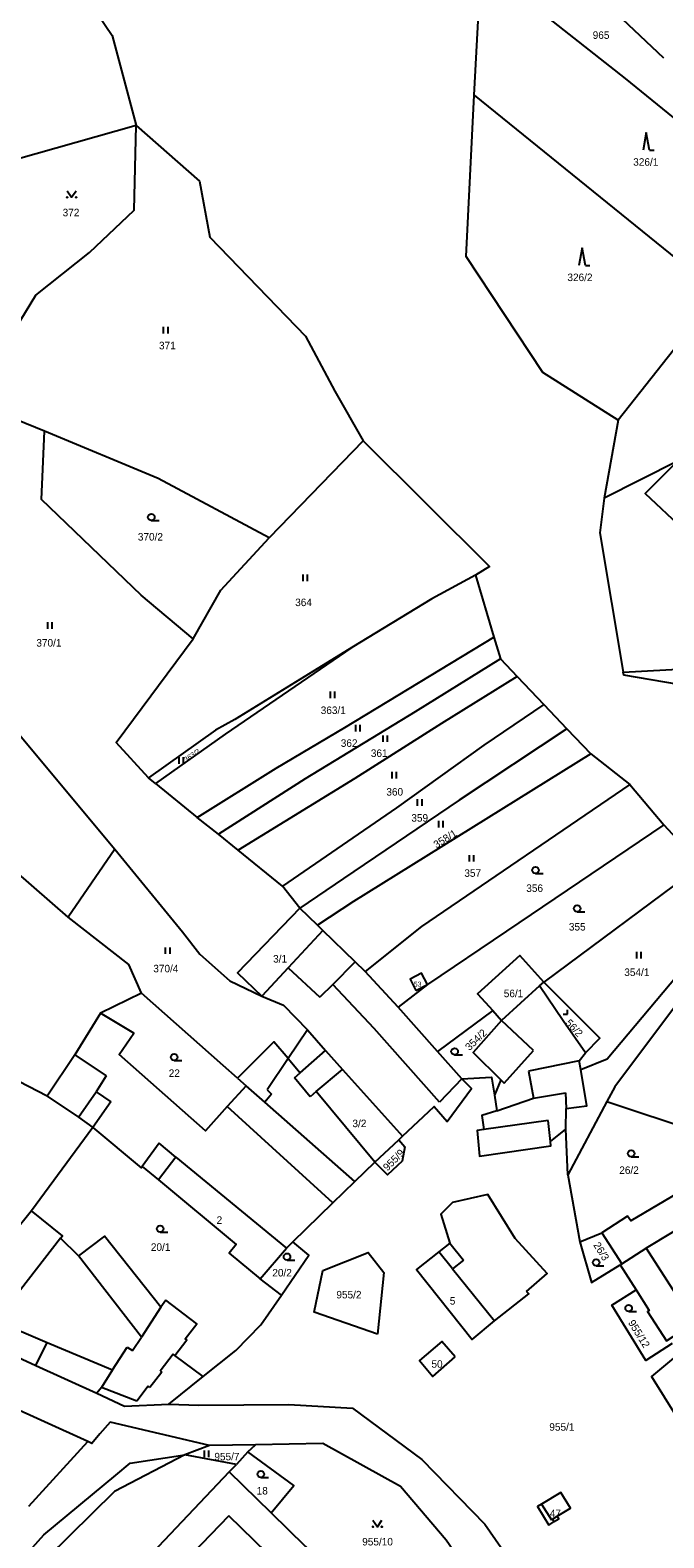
# Model space of a CAD drawing. Extents: x -7476540 to -746055, y -11317203 to -1129777.
# Drawn here: x -747956.4 to -747812.8, y -1130986.6 to -1130645.3 of the extents above; entities that cross this region are included whole.
import ezdxf

# ---------------------------------------------------------------- set-up
doc = ezdxf.new("R2010")
doc.units = 0
for name, color, linetype in [('Hranice parcel', 7, 'Continuous'), ('Parcelní čísla', 7, 'Continuous'), ('Vnitřní kresba', 7, 'Continuous'), ('Značky kultur', 7, 'Continuous')]:
    doc.layers.add(name, color=color, linetype=linetype)

msp = doc.modelspace()

# ---------------------------------------------------------------- linework, layer by layer
at = {"layer": 'Hranice parcel'}
for p, q in [((-747855.76, -1130660), (-747854.2, -1130630.54)), ((-747855.76, -1130660), (-747798.81, -1130706.12)), ((-747932.35, -1130666.92), (-747959.56, -1130674.56)), ((-747953.15, -1130736.09), (-747968.32, -1130729.96)), ((-747823.18, -1130733.56), (-747826.34, -1130751.29)), ((-747880.96, -1130738.26), (-747902.23, -1130760.25)), ((-747809.75, -1130742.85), (-747826.34, -1130751.29)), ((-747855.52, -1130768.71), (-747851.3, -1130782.72)), ((-747985.28, -1130773.23), (-747937.23, -1130830.7)), ((-747851.3, -1130782.72), (-747849.81, -1130787.66)), ((-747849.81, -1130787.66), (-747846.02, -1130791.65)), ((-747846.02, -1130791.65), (-747840.01, -1130797.96)), ((-747840.01, -1130797.96), (-747834.77, -1130803.46)), ((-747834.77, -1130803.46), (-747829.36, -1130809.14)), ((-747829.36, -1130809.14), (-747820.55, -1130816.09)), ((-747927.97, -1130815.84), (-747929.55, -1130814.55)), ((-747927.97, -1130815.84), (-747918.56, -1130823.54)), ((-747820.55, -1130816.09), (-747812.81, -1130825.22)), ((-747913.69, -1130827.28), (-747918.56, -1130823.54)), ((-747812.81, -1130825.22), (-747804.38, -1130834.32)), ((-747909.27, -1130830.92), (-747913.69, -1130827.28)), ((-747937.23, -1130830.7), (-747947.78, -1130846.14)), ((-747899.19, -1130839.1), (-747909.27, -1130830.92)), ((-747804.38, -1130834.32), (-747840.03, -1130860.79)), ((-747895.31, -1130844.05), (-747899.19, -1130839.1)), ((-747891.29, -1130847.94), (-747895.31, -1130844.05)), ((-747873.03, -1130866.5), (-747880.46, -1130858.39)), ((-747931.2, -1130863.28), (-747940.47, -1130867.84)), ((-747864.12, -1130876.49), (-747873.03, -1130866.5)), ((-747851.6, -1130867.26), (-747864.12, -1130876.49)), ((-747851.6, -1130867.26), (-747849.58, -1130869.48)), ((-747858.58, -1130882.72), (-747864.12, -1130876.49)), ((-747909.4, -1130882.58), (-747907.48, -1130884.27)), ((-747825.73, -1130887.83), (-747834.6, -1130904.4)), ((-747825.73, -1130887.83), (-747793.01, -1130898.76)), ((-747942.19, -1130893.69), (-747956.08, -1130912.6)), ((-747834.6, -1130904.4), (-747834.99, -1130894.09)), ((-747878.28, -1130901.53), (-747872.89, -1130896.5)), ((-747872.89, -1130896.5), (-747872.04, -1130895.7)), ((-747882.81, -1130905.92), (-747878.28, -1130901.53)), ((-747834.6, -1130904.4), (-747831.83, -1130919.6)), ((-747956.08, -1130912.6), (-747974.9, -1130935.77)), ((-747831.83, -1130919.6), (-747826.88, -1130917.6)), ((-747826.88, -1130917.6), (-747822.35, -1130924.58)), ((-747822.35, -1130924.58), (-747822.73, -1130924.82)), ((-747822.73, -1130924.82), (-747819.12, -1130930.45)), ((-747899.44, -1130931.65), (-747904.3, -1130927.98)), ((-747917.18, -1130950.1), (-747923.65, -1130945.33)), ((-747924.97, -1130956.33), (-747917.18, -1130950.1)), ((-747956.74, -1130979.41), (-747943.32, -1130964.83)), ((-747915.76, -1130965.72), (-747921.38, -1130967.81)), ((-747905.36, -1130965.53), (-747915.76, -1130965.72)), ((-747907.05, -1130967.14), (-747905.36, -1130965.53)), ((-747909.68, -1130969.99), (-747921.38, -1130967.81)), ((-747907.05, -1130967.14), (-747909.68, -1130969.99)), ((-747911.3, -1130971.64), (-747909.68, -1130969.99)), ((-747901.77, -1130980.96), (-747911.3, -1130971.64))]:
    msp.add_line(p, q, dxfattribs=at)
for points in [[(-747812.8, -1130651.64), (-747826.2, -1130639.05), (-747848.84, -1130625.02)], [(-747948.65, -1130630.54), (-747937.8, -1130646.48), (-747932.35, -1130666.92)], [(-747854.2, -1130630.54), (-747821.59, -1130656.28), (-747772.81, -1130695.9)], [(-747823.18, -1130733.56), (-747840.23, -1130722.79), (-747857.62, -1130696.55), (-747855.76, -1130660)], [(-747965.59, -1130718.16), (-747963.47, -1130718.96), (-747955.1, -1130705.31), (-747942.97, -1130695.63), (-747932.86, -1130686.09), (-747932.35, -1130666.92)], [(-747932.35, -1130666.92), (-747918.04, -1130679.51), (-747915.7, -1130692.18), (-747894.02, -1130714.58), (-747887.33, -1130727.05), (-747880.96, -1130738.26)], [(-747805.74, -1130716.29), (-747810.6, -1130717.76), (-747823.18, -1130733.56)], [(-747919.46, -1130783.07), (-747931.23, -1130773.21), (-747953.83, -1130751.57), (-747953.15, -1130736.09)], [(-747902.23, -1130760.25), (-747927.4, -1130746.77), (-747953.15, -1130736.09)], [(-747880.96, -1130738.26), (-747852.28, -1130766.74), (-747855.52, -1130768.71)], [(-747809.75, -1130742.85), (-747817.01, -1130750.2), (-747808.52, -1130758.22), (-747792.09, -1130768.69), (-747784.71, -1130772.17)], [(-747826.34, -1130751.29), (-747827.34, -1130759.1), (-747822, -1130790.67)], [(-747919.46, -1130783.07), (-747913.2, -1130772.11), (-747902.23, -1130760.25)], [(-747855.52, -1130768.71), (-747865.41, -1130774.06), (-747883.52, -1130785.07)], [(-747822, -1130790.67), (-747782.01, -1130788.46), (-747784.71, -1130772.17)], [(-747929.55, -1130814.55), (-747936.92, -1130806.6), (-747919.46, -1130783.07)], [(-747918.56, -1130823.54), (-747900.68, -1130812.35), (-747885.1, -1130803.15), (-747851.3, -1130782.72)], [(-747883.52, -1130785.07), (-747910.03, -1130801.35), (-747914.38, -1130803.79), (-747929.55, -1130814.55)], [(-747883.52, -1130785.07), (-747912.25, -1130804.68), (-747927.97, -1130815.84)], [(-747849.81, -1130787.66), (-747869.15, -1130799.59), (-747894.06, -1130814.79), (-747913.69, -1130827.28)], [(-747846.02, -1130791.65), (-747863.17, -1130802.29), (-747882.81, -1130814.71), (-747909.27, -1130830.92)], [(-747754.53, -1130790.17), (-747777.03, -1130805.89), (-747790.88, -1130796.57), (-747821.89, -1130791.29), (-747822, -1130790.67)], [(-747840.01, -1130797.96), (-747853.58, -1130807.15), (-747873.39, -1130821.38), (-747899.19, -1130839.1)], [(-747834.77, -1130803.46), (-747859.22, -1130819.6), (-747885.37, -1130837.32), (-747895.31, -1130844.05)], [(-747947.78, -1130846.14), (-747959.65, -1130835.75), (-748001.98, -1130807.92)], [(-747829.36, -1130809.14), (-747883.17, -1130842.59), (-747891.29, -1130847.94)], [(-747820.55, -1130816.09), (-747867.74, -1130848.23), (-747880.46, -1130858.39)], [(-747812.81, -1130825.22), (-747848.46, -1130849.27), (-747866.39, -1130861.37), (-747873.03, -1130866.5)], [(-747937.23, -1130830.7), (-747921.89, -1130849.4), (-747917.99, -1130854.46), (-747911.17, -1130860.49), (-747903.93, -1130864)], [(-747952.53, -1130886.62), (-747963.27, -1130881.1), (-747989.61, -1130862.33), (-748011.06, -1130841.51), (-748016.47, -1130840.3)], [(-747931.2, -1130863.28), (-747934.04, -1130856.8), (-747947.78, -1130846.14)], [(-747895.31, -1130844.05), (-747909.44, -1130858.68), (-747903.93, -1130864)], [(-747831.64, -1130880.59), (-747825.65, -1130878.15), (-747808.21, -1130857.46), (-747795.63, -1130843.76)], [(-747880.46, -1130858.39), (-747882.73, -1130856.2), (-747890.05, -1130849.13), (-747891.29, -1130847.94)], [(-747751.43, -1130846.33), (-747786.35, -1130849.61), (-747800.53, -1130857.22), (-747810.62, -1130866.79), (-747823.91, -1130884.54), (-747825.73, -1130887.83)], [(-747840.03, -1130860.79), (-747845.48, -1130854.8), (-747855.03, -1130863.49), (-747851.6, -1130867.26)], [(-747868.98, -1130862.72), (-747866.39, -1130861.37), (-747867.74, -1130858.78), (-747870.26, -1130860.14), (-747868.98, -1130862.72)], [(-747909.4, -1130882.58), (-747912.7, -1130879.65), (-747931.2, -1130863.28)], [(-747830.59, -1130876.82), (-747835.61, -1130869.57), (-747840.96, -1130861.66), (-747840.03, -1130860.79)], [(-747830.59, -1130876.82), (-747827.3, -1130873.5), (-747840.03, -1130860.79)], [(-747903.93, -1130864), (-747898.96, -1130866.03), (-747893.59, -1130871.58)], [(-747940.47, -1130867.84), (-747946.29, -1130877.28), (-747952.53, -1130886.62)], [(-747907.48, -1130884.27), (-747911.73, -1130888.98), (-747916.7, -1130894.49), (-747936.25, -1130877.17), (-747932.92, -1130872.33), (-747940.47, -1130867.84)], [(-747849.58, -1130869.48), (-747856.02, -1130876.74), (-747849.73, -1130882.95), (-747851.22, -1130886.4)], [(-747893.59, -1130871.58), (-747897.97, -1130878.1), (-747901.18, -1130874.36), (-747909.4, -1130882.58)], [(-747893.59, -1130871.58), (-747889.47, -1130876.3), (-747885.64, -1130880.57), (-747872.04, -1130895.7)], [(-747831.64, -1130880.59), (-747832, -1130878.65), (-747830.59, -1130876.82)], [(-747872.04, -1130895.7), (-747864.89, -1130888.95), (-747861.93, -1130892.38), (-747856.4, -1130884.91), (-747858.58, -1130882.72)], [(-747858.58, -1130882.72), (-747851.86, -1130882.31), (-747851.22, -1130886.4)], [(-747834.99, -1130894.09), (-747834.94, -1130889.44), (-747830.29, -1130888.84), (-747831.64, -1130880.59)], [(-747952.53, -1130886.62), (-747945.42, -1130891.38), (-747942.19, -1130893.69)], [(-747882.81, -1130905.92), (-747903.24, -1130887.99), (-747907.48, -1130884.27)], [(-747851.22, -1130886.4), (-747850.63, -1130889.96), (-747854.03, -1130890.99), (-747853.59, -1130894.17), (-747855.12, -1130894.39), (-747854.58, -1130900.2), (-747838.4, -1130897.9), (-747838.48, -1130896.91), (-747834.99, -1130894.09)], [(-747942.19, -1130893.69), (-747931.25, -1130902.83), (-747930.99, -1130902.52), (-747927.35, -1130905.55), (-747909.73, -1130920.21), (-747911.33, -1130922.13), (-747904.3, -1130927.98)], [(-747872.89, -1130896.5), (-747871.47, -1130898.11), (-747872.07, -1130901.37), (-747875.4, -1130904.41), (-747878.28, -1130901.53)], [(-747793.01, -1130898.76), (-747820.31, -1130914.83), (-747821.04, -1130913.77), (-747826.88, -1130917.6)], [(-747896.9, -1130919.58), (-747887.85, -1130910.81), (-747882.81, -1130905.92)], [(-747843.9, -1130930.84), (-747839.22, -1130926.8), (-747846.52, -1130918.84), (-747852.72, -1130908.9), (-747860.71, -1130910.68), (-747863.35, -1130913.36), (-747861.32, -1130919.89), (-747863.78, -1130921.85), (-747868.87, -1130925.9), (-747856.24, -1130941.74), (-747851.16, -1130937.49), (-747843.41, -1130931.39), (-747843.9, -1130930.84)], [(-747925.67, -1130932.84), (-747926.76, -1130934.36), (-747939.55, -1130918.32), (-747945.43, -1130922.74), (-747949.51, -1130918.78), (-747949.09, -1130918.27), (-747956.08, -1130912.6)], [(-747943.32, -1130964.83), (-747980.23, -1130948.11), (-748009.46, -1130932.87), (-748022.64, -1130922.41), (-748027.06, -1130916.24)], [(-747904.3, -1130927.98), (-747898.32, -1130921.01), (-747896.9, -1130919.58)], [(-747899.44, -1130931.65), (-747893.27, -1130922.65), (-747896.9, -1130919.58)], [(-747831.83, -1130919.6), (-747829.18, -1130928.84), (-747822.73, -1130924.82)], [(-747822.35, -1130924.58), (-747816.84, -1130921.05), (-747810.2, -1130931.39)], [(-747877.73, -1130940.47), (-747892.05, -1130935.51), (-747890.11, -1130926.12), (-747879.78, -1130921.99), (-747876.24, -1130926.56), (-747877.73, -1130940.47)], [(-747917.18, -1130950.1), (-747909.76, -1130944.17), (-747904.14, -1130938.37), (-747899.44, -1130931.65)], [(-747810.92, -1130942.58), (-747816.91, -1130946.43), (-747824.59, -1130933.96), (-747819.12, -1130930.45)], [(-747819.12, -1130930.45), (-747816.13, -1130935.12), (-747816.51, -1130935.36), (-747812.22, -1130942.04), (-747798.61, -1130933.2)], [(-747923.65, -1130945.33), (-747920.91, -1130941.82), (-747921.26, -1130941.54), (-747918.64, -1130938.18), (-747925.67, -1130932.84)], [(-747974.9, -1130935.77), (-747975.53, -1130936.55), (-747967.6, -1130941.88), (-747955.12, -1130947.63), (-747941.28, -1130953.85), (-747935.01, -1130956.79), (-747924.97, -1130956.33)], [(-747860.11, -1130945.6), (-747863.09, -1130942.14), (-747868.17, -1130946.48), (-747865.14, -1130950.05), (-747860.11, -1130945.6)], [(-747809.25, -1130944.84), (-747815.62, -1130950.1), (-747806.65, -1130964.52), (-747799.54, -1130960.27)], [(-747924.97, -1130956.33), (-747918.19, -1130956.61), (-747897.81, -1130956.39), (-747883.35, -1130957.23), (-747867.68, -1130968.89), (-747853.38, -1130983.52), (-747843.2, -1130998.16), (-747832.03, -1131034.24), (-747827.69, -1131050.62), (-747823.07, -1131065.32)], [(-747915.76, -1130965.72), (-747938.3, -1130960.4), (-747940.61, -1130963.08), (-747942.46, -1130965.22), (-747943.32, -1130964.83)], [(-747832.63, -1131062.43), (-747842.17, -1131030.42), (-747852.24, -1131001.44), (-747862.12, -1130987.14), (-747872.45, -1130974.99), (-747890.11, -1130965.25), (-747905.36, -1130965.53)], [(-747980.93, -1131019.45), (-747968.09, -1131002.39), (-747962.23, -1130995.86), (-747953.3, -1130985.9), (-747936.97, -1130972.39), (-747933.73, -1130969.71), (-747921.38, -1130967.81)], [(-747921.38, -1130967.81), (-747937.31, -1130976.12), (-747967.89, -1131006.15), (-747980.93, -1131019.45)], [(-747901.77, -1130980.96), (-747896.66, -1130974.79), (-747907.05, -1130967.14)], [(-747911.3, -1130971.64), (-747939.39, -1131001.36), (-747946.28, -1131008.68)], [(-747838.9, -1130983.72), (-747837.64, -1130982.94), (-747836.63, -1130982.32), (-747836.99, -1130981.73), (-747833.96, -1130979.87), (-747836.13, -1130976.33), (-747840.51, -1130978.98), (-747841.46, -1130979.55), (-747838.9, -1130983.72)], [(-747893.47, -1130989.15), (-747893.98, -1130988.57), (-747901.77, -1130980.96)]]:
    msp.add_lwpolyline(points, dxfattribs=at)
at = {"layer": 'Vnitřní kresba'}
for p, q in [((-747890.05, -1130849.13), (-747897.92, -1130857.56)), ((-747887.82, -1130861.32), (-747882.73, -1130856.2)), ((-747897.92, -1130857.56), (-747903.93, -1130864)), ((-747897.92, -1130857.56), (-747890.77, -1130864.23)), ((-747887.82, -1130861.32), (-747890.77, -1130864.23)), ((-747878.46, -1130871.28), (-747887.82, -1130861.32)), ((-747840.96, -1130861.66), (-747849.58, -1130869.48)), ((-747842.34, -1130876.27), (-747849.58, -1130869.48)), ((-747863.67, -1130887.95), (-747878.46, -1130871.28)), ((-747895.21, -1130881.31), (-747889.47, -1130876.3)), ((-747848.96, -1130883.68), (-747842.34, -1130876.27)), ((-747946.29, -1130877.28), (-747939.2, -1130881.99)), ((-747897.97, -1130878.1), (-747902.71, -1130885.17)), ((-747897.97, -1130878.1), (-747895.21, -1130881.31)), ((-747832, -1130878.65), (-747843.45, -1130880.95)), ((-747939.2, -1130881.99), (-747941.45, -1130885.62)), ((-747896.52, -1130882.45), (-747895.21, -1130881.31)), ((-747892.98, -1130886.77), (-747896.52, -1130882.45)), ((-747891.57, -1130885.56), (-747885.64, -1130880.57)), ((-747858.58, -1130882.72), (-747863.67, -1130887.95)), ((-747849.73, -1130882.95), (-747848.96, -1130883.68)), ((-747843.45, -1130880.95), (-747842.38, -1130887.09)), ((-747945.42, -1130891.38), (-747941.45, -1130885.62)), ((-747941.45, -1130885.62), (-747938.14, -1130887.93)), ((-747901.69, -1130886.19), (-747903.24, -1130887.99)), ((-747902.71, -1130885.17), (-747901.69, -1130886.19)), ((-747891.57, -1130885.56), (-747892.98, -1130886.77)), ((-747878.28, -1130901.53), (-747891.57, -1130885.56)), ((-747850.63, -1130889.96), (-747842.38, -1130887.09)), ((-747842.38, -1130887.09), (-747835.08, -1130885.88)), ((-747835.08, -1130885.88), (-747834.94, -1130889.44)), ((-747938.14, -1130887.93), (-747942.19, -1130893.69)), ((-747887.85, -1130910.81), (-747911.73, -1130888.98)), ((-747839.02, -1130892.13), (-747853.59, -1130894.17)), ((-747838.48, -1130896.91), (-747839.02, -1130892.13)), ((-747927.18, -1130897.3), (-747930.99, -1130902.52)), ((-747923.37, -1130900.43), (-747927.18, -1130897.3)), ((-747923.37, -1130900.43), (-747927.35, -1130905.55)), ((-747923.37, -1130900.43), (-747898.32, -1130921.01)), ((-747786.33, -1130902.63), (-747816.84, -1130921.05)), ((-747949.51, -1130918.78), (-747964.11, -1130937.48)), ((-747861.32, -1130919.89), (-747858.22, -1130923.72)), ((-747931.2, -1130941.16), (-747945.43, -1130922.74)), ((-747860.68, -1130925.7), (-747863.78, -1130921.85)), ((-747858.22, -1130923.72), (-747860.68, -1130925.7)), ((-747860.68, -1130925.7), (-747851.16, -1130937.49)), ((-747926.76, -1130934.36), (-747931.2, -1130941.16)), ((-747964.11, -1130937.48), (-747952.52, -1130942.42)), ((-747933.19, -1130944.19), (-747931.2, -1130941.16)), ((-747955.12, -1130947.63), (-747952.52, -1130942.42)), ((-747952.52, -1130942.42), (-747937.72, -1130948.61)), ((-747937.72, -1130948.61), (-747934.42, -1130943.46)), ((-747934.42, -1130943.46), (-747933.19, -1130944.19)), ((-747924, -1130945.06), (-747926.95, -1130948.85)), ((-747923.65, -1130945.33), (-747924, -1130945.06)), ((-747937.72, -1130948.61), (-747940.26, -1130952.54)), ((-747926.6, -1130949.12), (-747929.28, -1130952.56)), ((-747926.95, -1130948.85), (-747926.6, -1130949.12)), ((-747940.26, -1130952.54), (-747941.28, -1130953.85)), ((-747932.25, -1130955.65), (-747940.26, -1130952.54)), ((-747929.63, -1130952.29), (-747932.25, -1130955.65)), ((-747929.28, -1130952.56), (-747929.63, -1130952.29)), ((-747840.51, -1130978.98), (-747838.26, -1130982.51)), ((-747911.42, -1130981.63), (-747934.8, -1131005.8)), ((-747902.74, -1130990.02), (-747911.42, -1130981.63)), ((-747838.26, -1130982.51), (-747838.01, -1130982.35)), ((-747838.01, -1130982.35), (-747836.99, -1130981.73)), ((-747838.01, -1130982.35), (-747837.64, -1130982.94))]:
    msp.add_line(p, q, dxfattribs=at)
at = {"layer": 'Značky kultur'}
for p, q in [((-747816.78, -1130668.45), (-747817.53, -1130672.45)), ((-747816.03, -1130672.45), (-747816.78, -1130668.45)), ((-747816.03, -1130672.45), (-747815.03, -1130672.45)), ((-747831.32, -1130694.56), (-747832.07, -1130698.56)), ((-747830.57, -1130698.56), (-747831.32, -1130694.56)), ((-747830.57, -1130698.56), (-747829.57, -1130698.56)), ((-747926.16, -1130714), (-747926.16, -1130712.5)), ((-747925.16, -1130714), (-747925.16, -1130712.5)), ((-747928.95, -1130756.3), (-747927.2, -1130756.3)), ((-747894.53, -1130770.07), (-747894.53, -1130768.57)), ((-747893.53, -1130770.07), (-747893.53, -1130768.57)), ((-747952.41, -1130780.84), (-747952.41, -1130779.34)), ((-747951.41, -1130780.84), (-747951.41, -1130779.34)), ((-747888.33, -1130796.55), (-747888.33, -1130795.05)), ((-747887.33, -1130796.55), (-747887.33, -1130795.05)), ((-747882.59, -1130804.06), (-747882.59, -1130802.56)), ((-747881.59, -1130804.06), (-747881.59, -1130802.56)), ((-747876.43, -1130806.45), (-747876.43, -1130804.95)), ((-747875.43, -1130806.45), (-747875.43, -1130804.95)), ((-747922.64, -1130811.41), (-747922.64, -1130809.91)), ((-747921.64, -1130811.41), (-747921.64, -1130809.91)), ((-747874.4, -1130814.73), (-747874.4, -1130813.23)), ((-747873.4, -1130814.73), (-747873.4, -1130813.23)), ((-747868.61, -1130820.93), (-747868.61, -1130819.43)), ((-747867.61, -1130820.93), (-747867.61, -1130819.43)), ((-747863.81, -1130825.77), (-747863.81, -1130824.27)), ((-747862.81, -1130825.77), (-747862.81, -1130824.27)), ((-747856.86, -1130833.54), (-747856.86, -1130832.04)), ((-747855.86, -1130833.54), (-747855.86, -1130832.04)), ((-747841.92, -1130836.24), (-747840.17, -1130836.24)), ((-747832.44, -1130844.88), (-747830.69, -1130844.88)), ((-747925.71, -1130854.44), (-747925.71, -1130852.94)), ((-747924.71, -1130854.44), (-747924.71, -1130852.94)), ((-747818.95, -1130855.49), (-747818.95, -1130853.99)), ((-747817.95, -1130855.49), (-747817.95, -1130853.99)), ((-747835.66, -1130868.06), (-747834.66, -1130868.06)), ((-747834.66, -1130868.06), (-747834.66, -1130867.06)), ((-747923.77, -1130878.57), (-747922.02, -1130878.57)), ((-747860.22, -1130877.25), (-747858.47, -1130877.25)), ((-747820.23, -1130900.36), (-747818.48, -1130900.36)), ((-747926.92, -1130917.42), (-747925.17, -1130917.42)), ((-747898.2, -1130923.72), (-747896.45, -1130923.72)), ((-747828.13, -1130925.05), (-747826.38, -1130925.05)), ((-747820.78, -1130935.39), (-747819.03, -1130935.39)), ((-747916.89, -1130968.34), (-747916.89, -1130966.84)), ((-747915.89, -1130968.34), (-747915.89, -1130966.84)), ((-747904.13, -1130972.92), (-747902.38, -1130972.92))]:
    msp.add_line(p, q, dxfattribs=at)
for points in [[(-747948.01, -1130681.65), (-747947.01, -1130683.15), (-747946.01, -1130681.65)], [(-747878.72, -1130982.59), (-747877.72, -1130984.09), (-747876.72, -1130982.59)]]:
    msp.add_lwpolyline(points, dxfattribs=at)
for centre, radius in [((-747948.01, -1130683.15), 0.1), ((-747946.01, -1130683.15), 0.1), ((-747928.95, -1130755.55), 0.75), ((-747841.92, -1130835.49), 0.75), ((-747832.44, -1130844.13), 0.75), ((-747860.22, -1130876.5), 0.75), ((-747923.77, -1130877.82), 0.75), ((-747820.23, -1130899.61), 0.75), ((-747926.92, -1130916.67), 0.75), ((-747898.2, -1130922.97), 0.75), ((-747828.13, -1130924.3), 0.75), ((-747820.78, -1130934.64), 0.75), ((-747904.13, -1130972.17), 0.75), ((-747878.72, -1130984.09), 0.1), ((-747876.72, -1130984.09), 0.1)]:
    msp.add_circle(centre, radius, dxfattribs=at)

# ---------------------------------------------------------------- texts
at = {"layer": 'Parcelní čísla'}
for s, height, p in [('965', 1.7, (-747828.93, -1130647.28)), ('326/1', 1.7, (-747819.75, -1130676)), ('372', 1.7, (-747949.04, -1130687.44)), ('326/2', 1.7, (-747834.66, -1130702.11)), ('371', 1.7, (-747927.21, -1130717.55)), ('370/2', 1.7, (-747932, -1130760.85)), ('364', 1.7, (-747896.35, -1130775.69)), ('370/1', 1.7, (-747955, -1130784.85)), ('363/1', 1.7, (-747890.56, -1130800.11)), ('362', 1.7, (-747886.02, -1130807.55)), ('361', 1.7, (-747879.2, -1130809.83)), ('360', 1.7, (-747875.69, -1130818.58)), ('359', 1.7, (-747870.03, -1130824.48)), ('357', 1.7, (-747858.02, -1130836.97)), ('356', 1.7, (-747843.98, -1130840.39)), ('355', 1.7, (-747834.33, -1130849.13)), ('3/1', 1.7, (-747901.35, -1130856.38)), ('370/4', 1.7, (-747928.5, -1130858.59)), ('354/1', 1.7, (-747821.78, -1130859.42)), ('53', 1.14, (-747869.48, -1130861.84)), ('56/1', 1.7, (-747849.08, -1130864.22)), ('22', 1.7, (-747925, -1130882.27)), ('3/2', 1.7, (-747883.37, -1130893.64)), ('26/2', 1.7, (-747822.91, -1130904.23)), ('2', 1.7, (-747914.15, -1130915.53)), ('20/1', 1.7, (-747929.05, -1130921.64)), ('20/2', 1.7, (-747901.53, -1130927.44)), ('955/2', 1.7, (-747887.01, -1130932.41)), ('5', 1.7, (-747861.32, -1130933.81)), ('50', 1.7, (-747865.47, -1130948.1)), ('955/1', 1.7, (-747838.76, -1130962.36)), ('955/7', 1.7, (-747914.66, -1130969.07)), ('18', 1.7, (-747905.08, -1130976.8)), ('47', 1.7, (-747838.65, -1130981.92)), ('955/10', 1.7, (-747881.16, -1130988.33))]:
    msp.add_text(s, height=height, dxfattribs=at).set_placement(p)
for s, height, rotation, p in [('363/2', 1.14, 34, (-747921.06, -1130811.04)), ('358/1', 1.7, 32, (-747864.34, -1130830.6)), ('56/2', 1.7, 313, (-747835.26, -1130870.17)), ('354/2', 1.7, 44, (-747856.85, -1130876.45)), ('955/9', 1.7, 45, (-747875.44, -1130903.68)), ('26/3', 1.7, 302, (-747828.86, -1130920.32)), ('955/12', 1.7, 302, (-747820.99, -1130937.92))]:
    msp.add_text(s, height=height, rotation=rotation, dxfattribs=at).set_placement(p)

doc.saveas('drawing.dxf')
